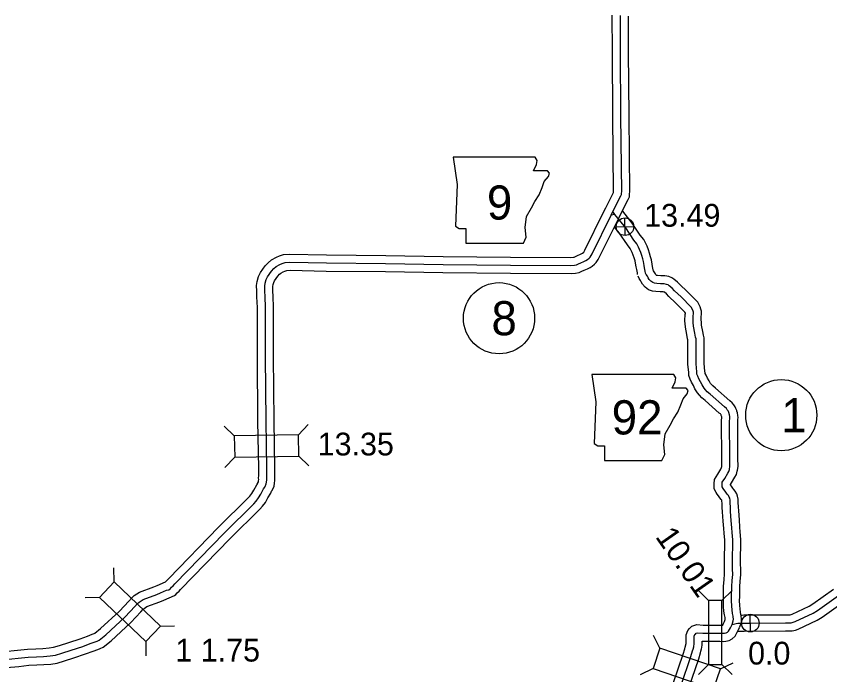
# Model space of a CAD drawing. Extents: x 31699 to 244310, y -8841 to 11474.
# Drawn here: x 101474 to 102480, y 4036 to 4850 of the extents above; entities that cross this region are included whole.
import ezdxf

# ---------------------------------------------------------------- set-up
doc = ezdxf.new("R2010")
doc.units = 0
for name, color, linetype in [('B_Logo', 7, 'Continuous'), ('G-ANNO-TEXT', 7, 'Continuous'), ('Level 21', 7, 'Continuous'), ('R_Border Notes', 7, 'Continuous'), ('R_XS_EARTHWORK_STAGE1', 7, 'Continuous'), ('R_XS_EARTHWORK_STAGE2', 7, 'Continuous'), ('S_WALL', 7, 'Continuous'), ('S_WALL_ANNOT', 7, 'Continuous')]:
    doc.layers.add(name, color=color, linetype=linetype)

msp = doc.modelspace()

# ---------------------------------------------------------------- linework, layer by layer
at = {"layer": 'B_Logo'}
for points in [[(101659.8, 4140.1), (101662.4, 4140.4), (101664.4, 4142.1), (101665.8, 4143.6), (101667.9, 4145.6), (101669.8, 4147.8), (101731.2, 4210.9), (101767.7, 4246.9), (101770.4, 4250.2), (101773.6, 4254.3), (101776.2, 4259), (101779.8, 4265.2), (101781.1, 4267.4), (101781.5, 4268.2), (101783.1, 4271.5), (101783.3, 4273.8), (101783.8, 4276.4), (101783.6, 4278.7), (101783.7, 4281.7), (101783.8, 4286.4), (101783.8, 4291.2), (101782.7, 4349.2), (101782.1, 4428.5), (101782, 4461.8), (101782, 4490), (101781.5, 4503), (101781.3, 4510.2), (101781.1, 4516.2), (101781.6, 4519.9), (101782.8, 4524.4), (101784.6, 4527.7), (101789.4, 4534.7), (101792.3, 4537.9), (101795.4, 4540.5), (101799.7, 4543), (101802.7, 4544.1), (101806.4, 4545.2), (101812.1, 4545.7), (101857.4, 4544.7), (101930.6, 4544.1), (102001.7, 4542.9), (102084.9, 4542.1), (102159.8, 4541.7), (102164.2, 4542), (102166.7, 4542.4), (102169, 4543.5), (102172.1, 4544.9), (102175.9, 4546.6), (102178.3, 4547.7), (102180.1, 4548.9), (102182.4, 4550.8), (102183.5, 4551.8), (102184.9, 4553.9), (102185.9, 4556.1), (102209.6, 4603.8), (102211.8, 4608.4), (102221.5, 4627.8), (102222.3, 4629.3), (102222.4, 4630), (102222.4, 4631.2), (102222.6, 4632.7), (102221.7, 4726.2), (102221.2, 4806.1), (102221, 4850.6)], [(102252.2, 4532.1), (102251.8, 4534.4), (102250.9, 4538.6), (102250.5, 4541.8), (102249.5, 4546.5), (102248.7, 4549.8), (102247.5, 4554), (102246.2, 4557.7), (102244.7, 4561.6), (102243.4, 4564.4), (102241.5, 4568.3), (102237.6, 4573), (102227.6, 4588.1), (102214.3, 4604.7), (102211.8, 4608.4)], [(102214.3, 4604.7), (102209.6, 4603.8)], [(102359, 4097.5), (102360.6, 4102.1), (102360.7, 4104.1), (102360.5, 4107.2), (102360.3, 4108.1), (102359.8, 4111.4), (102359, 4115.6), (102358.6, 4120.5), (102358.4, 4127.3), (102358.5, 4132), (102358.6, 4144.7), (102359.2, 4151.9), (102359.9, 4159.6), (102359.8, 4166.3), (102359.7, 4172.1), (102359.7, 4178.5), (102359.6, 4183.3), (102360.1, 4193.3), (102360, 4202.4), (102359.3, 4211.4), (102358.7, 4217.2), (102358.1, 4226.2), (102357.3, 4237.5), (102357, 4242.7), (102356.7, 4247.9), (102356.6, 4251.5), (102356.2, 4253.7), (102355.6, 4255.3), (102354.7, 4257.1), (102353.6, 4258.4), (102352.2, 4260.2), (102350.5, 4262.6), (102349, 4264.5), (102348, 4266), (102347, 4267.9), (102346.8, 4271.4), (102347, 4273.5), (102350, 4278.2), (102353.8, 4284.7), (102355.1, 4286.9), (102355.8, 4289.5), (102356, 4290.7), (102356.4, 4292.3), (102356.5, 4293.7), (102356.4, 4302.7), (102356.1, 4349.7), (102356.4, 4352.1), (102356.5, 4353.5), (102356.4, 4354.7), (102356, 4356.9), (102355.6, 4358.2), (102355.4, 4358.6), (102355.1, 4359.7), (102354.6, 4360.9), (102354.2, 4361.9), (102353.2, 4363.2), (102352, 4364.9), (102349.8, 4366.7), (102332.2, 4382.3), (102328.4, 4385.4), (102326.2, 4387.8), (102324.4, 4390), (102321.9, 4394.2), (102320, 4397.7), (102317.9, 4401.5), (102316.6, 4404.6), (102315.7, 4407.2), (102315.6, 4410.1), (102314.5, 4420), (102314.5, 4451), (102313.9, 4453.1), (102313, 4458), (102311.5, 4466.6), (102311.1, 4471), (102310.8, 4473.4), (102310.8, 4475.8), (102310.9, 4477.9), (102311, 4479.8), (102311.3, 4481.4), (102311.3, 4483.1), (102311.3, 4483.8), (102311, 4485.1), (102310.6, 4486.5), (102308.5, 4490.1), (102296, 4502.7), (102288, 4510.4), (102284.8, 4513.7), (102281.3, 4516.6), (102280, 4517.5), (102277.9, 4518.3), (102274.9, 4518.9), (102270.6, 4518.9), (102265.9, 4519.2), (102263.2, 4519.6), (102260.9, 4520.5), (102258.5, 4522.3), (102256.7, 4524.3), (102255.5, 4526.3), (102254.4, 4528.4), (102252.8, 4530.5), (102252.2, 4532.1)], [(101460.6, 4054.3), (101476.2, 4055.8), (101488.6, 4057.1), (101498.7, 4057.6), (101507.4, 4058.1), (101515.7, 4058.7), (101522.2, 4059.7), (101530.4, 4062), (101541.9, 4065.8), (101556, 4070.6), (101565.4, 4074), (101571.4, 4076.3), (101573.9, 4077.2), (101576.3, 4078.2), (101584.8, 4085), (101608.4, 4107.1), (101620.6, 4119.8), (101623.8, 4123.4), (101626, 4125.4), (101630.9, 4128.7), (101647.6, 4134.8), (101652.2, 4136.9), (101659.8, 4140.1)], [(102359, 4097.5), (102362.4, 4098.3), (102364.2, 4098.7), (102366.4, 4099.2), (102369, 4099.3), (102371.8, 4099.3), (102373.8, 4099.4), (102425.2, 4099.7), (102432.2, 4099.7), (102434.8, 4100.4), (102437.1, 4101.2), (102459.5, 4111.6), (102464.8, 4115), (102490.5, 4133.3)], [(102290.6, 4004.9), (102291.9, 4009.9), (102296.1, 4022.6), (102308.2, 4058.1), (102310.3, 4065), (102310.8, 4067.1), (102311.6, 4070), (102311.8, 4070.9), (102312.1, 4073.3), (102312.3, 4083), (102313.1, 4085.2), (102313.7, 4085.8), (102314.8, 4086.9), (102316.5, 4087.5), (102322.9, 4087), (102338.5, 4087), (102344.5, 4087), (102348.5, 4086.7), (102349.7, 4086.8), (102351.9, 4087.3), (102353.4, 4088.1), (102354.8, 4089.4), (102357.1, 4093.4), (102359, 4097.5)]]:
    msp.add_lwpolyline(points, dxfattribs=at)
at = {"layer": 'G-ANNO-TEXT'}
for points in [[(102014.1, 4675.4), (102019.2, 4641.6), (102017, 4590.3), (102021.5, 4587.5), (102029.9, 4587.5), (102029.9, 4569.4), (102101, 4569.4), (102104.4, 4576.8), (102103.2, 4588.6), (102104.9, 4602.1), (102111.1, 4612.9), (102115.1, 4620.7), (102120.7, 4629.2), (102124.1, 4638.2), (102126.9, 4645.6), (102132, 4651.8), (102133.1, 4655.7), (102130.9, 4658.5), (102113.4, 4658.5), (102117.3, 4666.4), (102117.9, 4671.5), (102115.6, 4675.4)], [(102185.6, 4406.6), (102190.7, 4372.8), (102188.4, 4321.5), (102192.9, 4318.7), (102201.4, 4318.7), (102201.4, 4300.6), (102272.4, 4300.6), (102275.8, 4308), (102274.7, 4319.8), (102276.4, 4333.3), (102282.6, 4344), (102286.5, 4351.9), (102292.2, 4360.4), (102295.6, 4369.4), (102298.4, 4376.8), (102303.5, 4383), (102304.6, 4386.9), (102302.3, 4389.7), (102284.8, 4389.7), (102288.8, 4397.6), (102289.4, 4402.7), (102287, 4406.6)]]:
    msp.add_lwpolyline(points, close=True, dxfattribs=at)
at = {"layer": 'Level 21'}
for p, q in [((102227, 4578.8), (102226.5, 4600.5)), ((102215.9, 4589.4), (102237.6, 4589.9)), ((102382, 4088.4), (102381.5, 4110.1)), ((102370.9, 4099), (102392.6, 4099.5))]:
    msp.add_line(p, q, dxfattribs=at)
for centre in [(102226.7, 4589.6), (102381.7, 4099.3)]:
    msp.add_circle(centre, 10.9, dxfattribs=at)
at = {"layer": 'R_Border Notes'}
for centre in [(102070.9, 4476.4), (102419.9, 4356.5)]:
    msp.add_circle(centre, 44, dxfattribs=at)
at = {"layer": 'R_XS_EARTHWORK_STAGE1'}
for p, q in [((101743.5, 4330.9), (101730.8, 4343.1)), ((101822.7, 4332.3), (101834.9, 4345)), ((101823.2, 4305.9), (101835.8, 4293.7)), ((101744, 4304.5), (101731.8, 4291.8)), ((101594.9, 4150.2), (101594.5, 4167.8)), ((102330, 4127.3), (102317.6, 4139.7)), ((102346.6, 4127.2), (102359, 4139.7)), ((101576.6, 4131.1), (101559, 4130.7)), ((102330, 4127.3), (102330, 4048.1)), ((102346.6, 4127.2), (102330, 4127.3)), ((102346.5, 4048), (102346.6, 4127.2)), ((101652.1, 4095.4), (101669.7, 4095.8)), ((101633.9, 4076.4), (101634.2, 4058.8)), ((102269.9, 4068.2), (102262.1, 4084.1)), ((102330, 4048.1), (102317.5, 4035.6)), ((102330, 4048.1), (102346.5, 4048)), ((102344.8, 4042.6), (102360.6, 4050.3)), ((102346.5, 4048), (102359, 4035.6)), ((102261.3, 4043.3), (102245.5, 4035.5))]:
    msp.add_line(p, q, dxfattribs=at)
for points in [[(101822.7, 4332.3), (101743.5, 4330.9), (101744, 4304.5), (101823.2, 4305.9)], [(101652.1, 4095.4), (101594.9, 4150.2), (101576.6, 4131.1), (101633.9, 4076.4)], [(102344.8, 4042.6), (102269.9, 4068.2), (102261.3, 4043.3), (102336.2, 4017.6)]]:
    msp.add_lwpolyline(points, close=True, dxfattribs=at)
at = {"layer": 'R_XS_EARTHWORK_STAGE2'}
for points in [[(101658.6, 4150.5), (101658.7, 4150.6), (101660.6, 4152.5), (101662.5, 4154.6), (101724.1, 4217.9), (101760.3, 4253.7), (101762.7, 4256.5), (101765.3, 4259.8), (101767.5, 4263.9), (101771.2, 4270.2), (101772.5, 4272.5), (101772.7, 4273), (101773.3, 4274.2), (101773.4, 4275.1), (101773.7, 4276.9), (101773.6, 4278.6), (101773.7, 4282), (101773.8, 4286.5), (101773.8, 4291.1), (101772.7, 4349), (101772.1, 4428.5), (101772, 4461.8), (101772, 4489.8), (101771.5, 4502.7), (101771.3, 4509.9), (101771.1, 4516.7), (101771.8, 4521.9), (101773.5, 4528.1), (101776, 4532.9), (101781.6, 4541), (101785.4, 4545.1), (101789.7, 4548.7), (101795.5, 4552.1), (101799.5, 4553.5), (101804.4, 4555.1), (101811.8, 4555.7), (101857.6, 4554.7), (101930.8, 4554.1), (102001.8, 4552.9), (102085, 4552.1), (102159.6, 4551.7), (102163.1, 4551.9), (102163.7, 4552), (102164.7, 4552.5), (102168, 4554.1), (102171.8, 4555.7), (102173.3, 4556.4), (102174.2, 4557), (102175.7, 4558.2), (102176.1, 4558.8), (102176.9, 4560.4), (102200.6, 4608.2), (102202.9, 4612.8), (102212.5, 4632), (102212.6, 4633), (102211.7, 4726.1), (102211.2, 4806), (102211, 4851)], [(101669.6, 4133.4), (101671.2, 4134.7), (101673, 4136.6), (101675.2, 4138.8), (101677.1, 4141), (101738.3, 4203.8), (101775, 4240.1), (101778.2, 4243.9), (101782, 4248.7), (101784.9, 4254.1), (101788.5, 4260.2), (101789.7, 4262.4), (101790.3, 4263.4), (101792.9, 4268.7), (101793.3, 4272.5), (101793.8, 4275.9), (101793.6, 4278.9), (101793.7, 4281.5), (101793.8, 4286.2), (101793.8, 4291.2), (101792.7, 4349.3), (101792.1, 4428.6), (101792, 4461.8), (101792, 4490.2), (101791.4, 4503.3), (101791.3, 4510.4), (101791.1, 4515.7), (101791.4, 4518), (101792.2, 4520.7), (101793.1, 4522.5), (101797.3, 4528.5), (101799.3, 4530.7), (101801.2, 4532.3), (101804, 4533.9), (101806, 4534.6), (101808.3, 4535.4), (101812.4, 4535.7), (101857.3, 4534.7), (101930.5, 4534.1), (102001.5, 4532.9), (102084.9, 4532.1), (102160.1, 4531.7), (102165.3, 4532), (102169.8, 4532.8), (102173.3, 4534.4), (102176.2, 4535.8), (102180.1, 4537.5), (102183.4, 4539), (102186, 4540.9), (102189.1, 4543.3), (102191.2, 4545.5), (102193.6, 4548.9), (102194.9, 4551.7), (102218.6, 4599.4), (102220.8, 4603.9), (102230.5, 4623.3), (102232.1, 4626.5), (102232.4, 4629.3), (102232.4, 4630.6), (102232.6, 4632.3), (102231.7, 4726.3), (102231.2, 4806.1), (102231, 4850.1)], [(102261.8, 4535.2), (102261.7, 4536.3), (102260.8, 4540.3), (102260.3, 4543.4), (102259.3, 4548.6), (102258.4, 4552.4), (102257, 4557), (102255.7, 4561.1), (102253.9, 4565.6), (102252.4, 4568.7), (102250, 4573.8), (102245.6, 4579), (102235.6, 4594), (102223.8, 4608.9)], [(102242.3, 4530.6), (102242, 4532.6), (102241.1, 4536.8), (102240.6, 4540.1), (102239.7, 4544.3), (102239.1, 4547.3), (102237.9, 4551), (102236.8, 4554.3), (102235.6, 4557.6), (102234.4, 4560.1), (102233.1, 4562.8), (102229.6, 4567), (102219.5, 4582.2), (102214.3, 4588.6)], [(102349.8, 4101.4), (102350.7, 4103.9), (102350.7, 4103.9), (102350.6, 4105.8), (102350.5, 4106.2), (102349.9, 4109.7), (102349.1, 4114.3), (102348.6, 4119.9), (102348.4, 4127.3), (102348.5, 4132.2), (102348.6, 4145.1), (102349.2, 4152.7), (102349.9, 4160.1), (102349.8, 4166.1), (102349.7, 4172), (102349.7, 4178.4), (102349.6, 4183.5), (102350.1, 4193.5), (102350, 4201.9), (102349.3, 4210.5), (102348.8, 4216.4), (102348.1, 4225.5), (102347.3, 4236.8), (102347, 4242.2), (102346.8, 4247.5), (102346.6, 4250.3), (102346.5, 4251.1), (102346.4, 4251.4), (102345.8, 4252.1), (102344.1, 4254.3), (102342.4, 4256.7), (102340.8, 4258.8), (102339.5, 4260.8), (102337, 4265.2), (102336.8, 4271.7), (102337.3, 4276.8), (102341.4, 4283.5), (102345.2, 4289.7), (102345.7, 4290.7), (102346, 4291.9), (102346.3, 4292.9), (102346.5, 4293.9), (102346.5, 4294.1), (102346.4, 4302.7), (102346.1, 4350.5), (102346.5, 4353.1), (102346.5, 4353.3), (102346.5, 4353.4), (102346.3, 4354.3), (102345.7, 4356.3), (102345.5, 4356.8), (102345.2, 4357.2), (102344.6, 4358), (102343.3, 4359.1), (102325.7, 4374.7), (102321.5, 4378.1), (102318.6, 4381.3), (102316.2, 4384.2), (102313.2, 4389.2), (102311.2, 4393), (102308.9, 4397.2), (102307.3, 4401), (102305.8, 4405.4), (102305.7, 4409.3), (102304.5, 4419.4), (102304.5, 4449.7), (102304.1, 4450.9), (102303.2, 4456.3), (102301.6, 4465.3), (102301.2, 4470), (102300.8, 4472.7), (102300.8, 4476.1), (102300.9, 4478.5), (102301.1, 4480.9), (102301.3, 4482.3), (102301.3, 4482.5), (102301.3, 4482.6), (102300.5, 4484), (102289, 4495.6), (102281, 4503.3), (102278, 4506.4), (102275.4, 4508.5), (102275.1, 4508.7), (102273.8, 4508.9), (102270.3, 4508.9), (102264.9, 4509.3), (102260.7, 4509.8), (102255.9, 4511.7), (102251.7, 4514.9), (102248.5, 4518.4), (102246.7, 4521.5), (102246, 4523), (102244, 4525.6), (102242.8, 4528.5)], [(102368.3, 4093.8), (102370.6, 4100.3), (102370.7, 4104.3), (102370.4, 4108.5), (102370.1, 4110), (102369.7, 4113), (102368.9, 4117), (102368.5, 4121.1), (102368.4, 4127.3), (102368.5, 4131.8), (102368.6, 4144.3), (102369.1, 4151.1), (102369.9, 4159.2), (102369.8, 4166.4), (102369.7, 4172.2), (102369.7, 4178.6), (102369.6, 4183.1), (102370.1, 4193.1), (102370, 4202.8), (102369.2, 4212.3), (102368.7, 4218), (102368.1, 4226.9), (102367.3, 4238.1), (102367, 4243.3), (102366.7, 4248.4), (102366.5, 4252.7), (102365.9, 4256.2), (102364.9, 4259.2), (102363.1, 4262.7), (102361.3, 4264.7), (102360.2, 4266.2), (102358.5, 4268.6), (102357.1, 4270.3), (102357, 4270.6), (102358.5, 4273), (102362.5, 4279.7), (102364.4, 4283.1), (102365.5, 4287.2), (102365.8, 4288.5), (102366.3, 4290.7), (102366.5, 4293.4), (102366.4, 4302.8), (102366.1, 4349), (102366.4, 4351.1), (102366.5, 4353.6), (102366.4, 4356), (102365.7, 4359.2), (102365.1, 4361.5), (102364.8, 4362.1), (102364.5, 4363.2), (102363.9, 4364.7), (102363, 4366.9), (102361.2, 4369.2), (102359.3, 4371.8), (102356.3, 4374.3), (102338.7, 4389.9), (102335.3, 4392.6), (102333.8, 4394.3), (102332.6, 4395.8), (102330.6, 4399.1), (102328.8, 4402.4), (102326.9, 4405.9), (102326, 4408.2), (102325.7, 4409), (102325.6, 4410.8), (102324.5, 4420.6), (102324.5, 4452.3), (102323.7, 4455.3), (102322.8, 4459.8), (102321.4, 4467.9), (102321.1, 4472.1), (102320.8, 4474), (102320.8, 4475.6), (102320.9, 4477.4), (102321, 4478.8), (102321.3, 4480.4), (102321.3, 4483), (102321.3, 4485.1), (102320.6, 4487.8), (102319.8, 4490.5), (102316.6, 4496.2), (102303, 4509.9), (102295, 4517.5), (102291.6, 4521), (102287.2, 4524.7), (102284.4, 4526.5), (102280.7, 4527.9), (102275.9, 4528.9), (102270.9, 4528.9), (102266.9, 4529.2), (102265.8, 4529.3), (102265.2, 4529.8), (102264.8, 4530.3), (102264.3, 4531.2), (102262.9, 4533.8), (102261.9, 4535.1)], [(101459.5, 4064.3), (101475.2, 4065.7), (101487.8, 4067.1), (101498.2, 4067.5), (101506.7, 4068.1), (101514.5, 4068.6), (101520, 4069.5), (101527.5, 4071.6), (101538.8, 4075.3), (101552.7, 4080.1), (101561.9, 4083.4), (101567.9, 4085.7), (101570.3, 4086.5), (101571.1, 4086.9), (101578.2, 4092.6), (101601.4, 4114.2), (101613.2, 4126.6), (101616.6, 4130.4), (101619.8, 4133.3), (101626.4, 4137.7), (101643.9, 4144.1), (101648.3, 4146), (101658.5, 4150.4)], [(102370.7, 4109.3), (102371.5, 4109.3), (102373.5, 4109.4), (102425.1, 4109.7), (102431, 4109.7), (102432, 4110), (102433.3, 4110.4), (102454.6, 4120.3), (102459.1, 4123.3), (102484.7, 4141.5)], [(101461.8, 4044.4), (101477.2, 4045.8), (101489.3, 4047.2), (101499.3, 4047.6), (101508.1, 4048.1), (101516.8, 4048.7), (101524.3, 4049.9), (101533.3, 4052.5), (101545.1, 4056.3), (101559.3, 4061.2), (101568.9, 4064.6), (101574.8, 4066.9), (101577.5, 4067.9), (101581.4, 4069.5), (101591.3, 4077.5), (101615.4, 4099.9), (101628, 4113.1), (101630.9, 4116.4), (101632.2, 4117.5), (101635.5, 4119.7), (101651.3, 4125.6), (101656.2, 4127.7), (101669.6, 4133.4)], [(102366, 4088.8), (102366.2, 4088.9), (102367.7, 4089.2), (102369.3, 4089.3), (102372, 4089.3), (102374, 4089.4), (102425.3, 4089.7), (102433.4, 4089.7), (102437.7, 4090.8), (102440.9, 4091.9), (102464.4, 4102.8), (102470.4, 4106.8), (102496.3, 4125.2)], [(102281.1, 4008.1), (102282.3, 4012.7), (102286.6, 4025.8), (102298.7, 4061.1), (102300.6, 4067.6), (102301.1, 4069.6), (102301.9, 4072.4), (102301.9, 4072.7), (102302.2, 4074.1), (102302.3, 4084.9), (102304.4, 4090.4), (102306.4, 4092.7), (102309.5, 4095.7), (102315.3, 4097.6), (102323.3, 4097), (102338.5, 4097), (102344.9, 4097), (102347.5, 4096.8), (102348.2, 4098), (102349.8, 4101.4)], [(102300.2, 4001.9), (102301.5, 4007.1), (102305.6, 4019.4), (102317.8, 4055), (102320, 4062.4), (102320.5, 4064.6), (102321.3, 4067.6), (102321.6, 4069), (102322.1, 4072.4), (102322.2, 4077), (102338.6, 4077), (102344, 4077), (102348.6, 4076.6), (102351.2, 4076.9), (102355.4, 4077.7), (102359.2, 4079.9), (102362.8, 4083), (102366, 4088.8), (102368.3, 4093.7)]]:
    msp.add_lwpolyline(points, dxfattribs=at)

# ---------------------------------------------------------------- texts
at = {"layer": 'G-ANNO-TEXT'}
for s, height, p in [('9', 42.2, (102055.9, 4598.4)), ('92', 42.24, (102210.2, 4332.7))]:
    msp.add_text(s, height=height, dxfattribs=at).set_placement(p)
at = {"layer": 'R_Border Notes'}
for s, p in [('8', (102061.5, 4455.3)), ('1', (102419.9, 4335.4))]:
    msp.add_text(s, height=42.2, dxfattribs=at).set_placement(p)
at = {"layer": 'S_WALL'}
for s, p in [('13.35', (101846.6, 4306.7)), ('1 1.75', (101670.6, 4051.8))]:
    msp.add_text(s, height=28.16, dxfattribs=at).set_placement(p)
msp.add_text('10.01', height=28.16, rotation=305, dxfattribs=at).set_placement((102263.4, 4206.1))
at = {"layer": 'S_WALL_ANNOT'}
for s, p in [('13.49', (102250.4, 4589.6)), ('0.0', (102378.9, 4048.1))]:
    msp.add_text(s, height=28.16, dxfattribs=at).set_placement(p)

doc.saveas('drawing.dxf')
